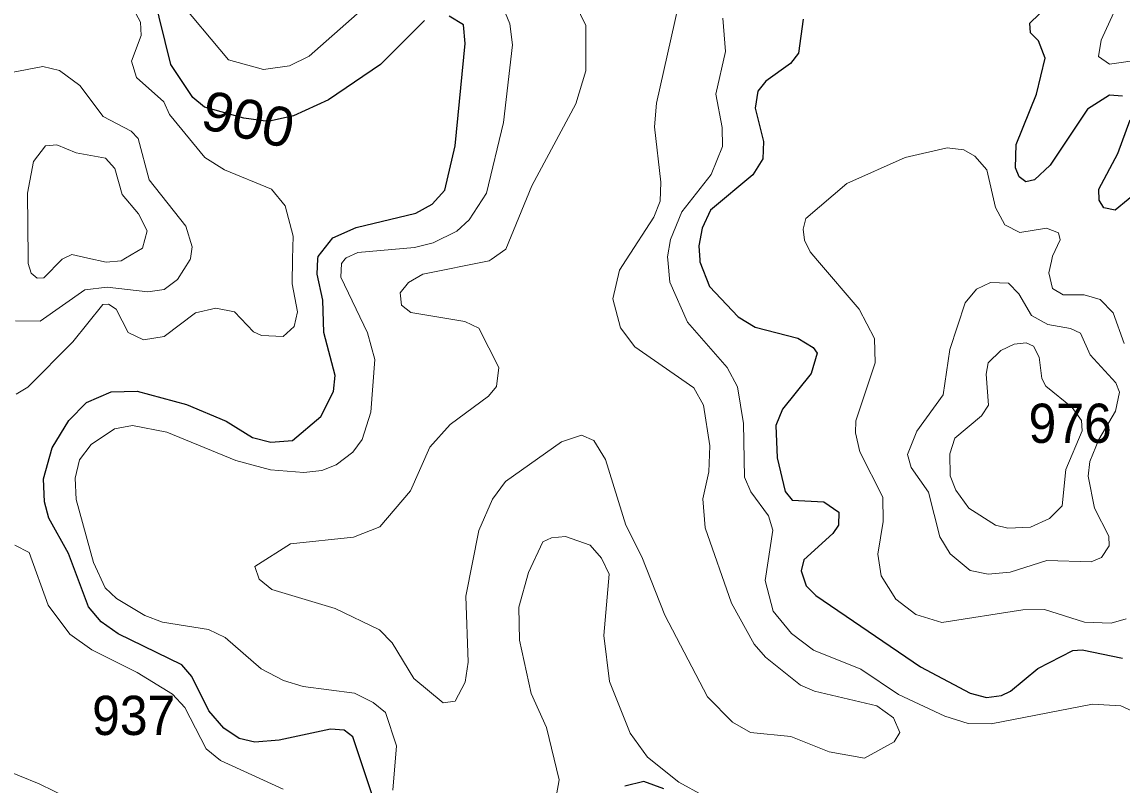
# Model space of a CAD drawing. Extents: x 473.9 to 500, y 7733.1 to 7760.8.
# Drawn here: x 488.002 to 490.243, y 7751.572 to 7753.127 of the extents above; entities that cross this region are included whole.
import ezdxf
from ezdxf.enums import TextEntityAlignment as Align

# ---------------------------------------------------------------- set-up
doc = ezdxf.new("R2010")
doc.units = 0
doc.header["$LTSCALE"] = 0.032
doc.layers.add('1', color=7, linetype='Continuous', lineweight=25)
doc.layers.add('2', color=7, linetype='Continuous', lineweight=13)
doc.layers.add('21', color=7, linetype='Continuous')
doc.layers.add('61', color=7, linetype='Continuous')

msp = doc.modelspace()

# ---------------------------------------------------------------- linework, layer by layer
at = {"layer": '1'}
for points in [[(490.0556, 7753.125), (490.1532, 7753.2201)], [(488.8218, 7753.1307), (488.7321, 7753.0411), (488.6264, 7752.9688), (488.555, 7752.9361), (488.5032, 7752.9247), (488.4537, 7752.9313), (488.3738, 7752.9536), (488.3498, 7752.9732), (488.3051, 7753.0408), (488.2698, 7753.1849)], [(488.3274, 7751.8169), (488.1979, 7751.88), (488.1633, 7751.9046), (488.1372, 7751.9352), (488.0963, 7752.0442), (488.0568, 7752.1157), (488.0478, 7752.149), (488.0456, 7752.196), (488.0636, 7752.259), (488.097, 7752.315), (488.1334, 7752.3518), (488.1833, 7752.3732), (488.2365, 7752.3751), (488.337, 7752.3475), (488.418, 7752.3137), (488.4715, 7752.2803), (488.5087, 7752.2708), (488.5527, 7752.2742), (488.6106, 7752.323), (488.6365, 7752.374), (488.6397, 7752.407), (488.6166, 7752.4946), (488.6147, 7752.5604), (488.6035, 7752.6132), (488.6049, 7752.6445), (488.6051, 7752.6495), (488.6355, 7752.6877), (488.6828, 7752.7085), (488.8045, 7752.738), (488.8375, 7752.7559), (488.8634, 7752.7845), (488.8847, 7752.8749), (488.905, 7753.0839), (488.9013, 7753.1217), (488.872, 7753.139)], [(489.5934, 7753.1335), (489.5841, 7753.0638), (489.5675, 7753.0428), (489.5174, 7753.0068), (489.501, 7752.9866), (489.4961, 7752.9521), (489.5129, 7752.8836), (489.5112, 7752.8484), (489.4908, 7752.8158), (489.4048, 7752.7439), (489.3879, 7752.7071), (489.3811, 7752.6711), (489.3831, 7752.6421), (489.3834, 7752.6382), (489.4026, 7752.5882), (489.4615, 7752.5264), (489.496, 7752.505), (489.5828, 7752.483), (489.6143, 7752.4641), (489.6219, 7752.4525), (489.6098, 7752.4108), (489.5518, 7752.3381), (489.5378, 7752.3047), (489.5407, 7752.2392), (489.5568, 7752.1702), (489.5715, 7752.1525), (489.6357, 7752.1492), (489.6665, 7752.1282), (489.6656, 7752.1019), (489.6544, 7752.0847), (489.5952, 7752.0308), (489.5893, 7752.0086), (489.5999, 7751.9782), (489.6195, 7751.9586), (489.8326, 7751.8129), (489.9337, 7751.7592), (489.9671, 7751.7506), (489.9979, 7751.7544), (490.0159, 7751.763), (490.0717, 7751.8095), (490.1434, 7751.8461), (490.1622, 7751.8474), (490.2441, 7751.8304)], [(490.2447, 7752.9761), (490.2176, 7752.9786), (490.1728, 7752.95), (490.0969, 7752.8355), (490.0648, 7752.8054), (490.0472, 7752.8018), (490.0337, 7752.8118), (490.0265, 7752.83), (490.0278, 7752.8775), (490.0693, 7752.9802), (490.0869, 7753.0535), (490.0735, 7753.0887), (490.0571, 7753.1051), (490.0556, 7753.125)], [(490.2823, 7752.7871), (490.2296, 7752.7436), (490.2061, 7752.7487), (490.1968, 7752.7641), (490.1963, 7752.7867), (490.2351, 7752.8591), (490.2597, 7752.9277)], [(488.7226, 7751.5297), (488.6762, 7751.6702), (488.6586, 7751.684), (488.6306, 7751.6855), (488.526, 7751.6632), (488.4764, 7751.659), (488.4444, 7751.667), (488.413, 7751.6879), (488.3824, 7751.7233), (488.3481, 7751.7934), (488.3274, 7751.8169)], [(489.3094, 7751.564), (489.2687, 7751.5793), (489.2303, 7751.5696)]]:
    msp.add_lwpolyline(points, dxfattribs=at)
at = {"layer": '2'}
for points in [[(488.7559, 7751.8615), (488.7305, 7751.888), (488.64, 7751.9317), (488.5112, 7751.9703), (488.4854, 7751.9919), (488.4765, 7752.0176), (488.5489, 7752.0636), (488.6775, 7752.0774), (488.7312, 7752.098), (488.7932, 7752.172), (488.8331, 7752.2604), (488.8744, 7752.3069), (488.9524, 7752.3649), (488.9684, 7752.3847), (488.9737, 7752.423), (488.9326, 7752.5035), (488.9042, 7752.5168), (488.7942, 7752.535), (488.7753, 7752.5504), (488.7723, 7752.5753), (488.7893, 7752.5964), (488.8185, 7752.6131), (488.9537, 7752.6407), (488.9576, 7752.6434), (488.988, 7752.664), (489.0404, 7752.7932), (489.1305, 7752.9609), (489.1511, 7753.0279), (489.1511, 7753.1201), (489.0847, 7753.2568)], [(490.3078, 7753.2568), (490.2264, 7753.1469), (490.2007, 7753.0907), (490.1957, 7753.0573), (490.2176, 7753.0414), (490.2886, 7753.0514)], [(487.9898, 7752.3685), (488.0137, 7752.383), (488.1051, 7752.4751), (488.1668, 7752.5516), (488.178, 7752.5522), (488.1939, 7752.5417), (488.2183, 7752.4944), (488.2492, 7752.4797), (488.2913, 7752.4864), (488.3552, 7752.5347), (488.3971, 7752.5442), (488.4348, 7752.5364), (488.4739, 7752.496), (488.4902, 7752.4885), (488.5337, 7752.4862), (488.5564, 7752.5067), (488.5632, 7752.5369), (488.5521, 7752.5938), (488.5533, 7752.6446), (488.5544, 7752.6909), (488.538, 7752.7526), (488.51, 7752.7868), (488.4143, 7752.826), (488.3747, 7752.8514), (488.3023, 7752.9391), (488.2911, 7752.965), (488.2352, 7753.0142), (488.2249, 7753.0477), (488.2447, 7753.1002), (488.2431, 7753.127), (488.2035, 7753.2021)], [(488.9767, 7753.17), (488.9959, 7753.1239), (489.0016, 7753.0806), (488.9832, 7752.9228), (488.9487, 7752.7787), (488.9128, 7752.7238), (488.8882, 7752.7009), (488.8398, 7752.677), (488.8018, 7752.6678), (488.6861, 7752.6573), (488.6623, 7752.6469), (488.6603, 7752.6443), (488.6532, 7752.635), (488.6512, 7752.6071), (488.7061, 7752.4938), (488.7209, 7752.4394), (488.7126, 7752.3322), (488.6951, 7752.2765), (488.6758, 7752.2508), (488.6422, 7752.2246), (488.6126, 7752.2128), (488.5761, 7752.2088), (488.5081, 7752.2147), (488.4373, 7752.2335), (488.297, 7752.2912), (488.2267, 7752.3046), (488.1903, 7752.298), (488.1425, 7752.2663), (488.119, 7752.2351), (488.1103, 7752.1978), (488.1119, 7752.1543), (488.1477, 7752.0256), (488.1716, 7751.974), (488.1947, 7751.9521), (488.252, 7751.9176), (488.2884, 7751.9042), (488.3816, 7751.8893), (488.4158, 7751.8727), (488.4891, 7751.8089), (488.5344, 7751.7852), (488.5747, 7751.7728), (488.6791, 7751.7594), (488.7176, 7751.7401), (488.7425, 7751.7196), (488.7652, 7751.6519), (488.7578, 7751.5612)], [(488.3133, 7753.1817), (488.4224, 7753.0501), (488.4941, 7753.0308), (488.5472, 7753.0379), (488.5873, 7753.0581), (488.685, 7753.1444)], [(489.3398, 7753.1619), (489.2948, 7752.9619), (489.291, 7752.9136), (489.3038, 7752.8012), (489.3022, 7752.762), (489.2892, 7752.7293), (489.2327, 7752.6425), (489.2191, 7752.6216), (489.2059, 7752.563), (489.2217, 7752.5037), (489.2507, 7752.4655), (489.3706, 7752.3815), (489.3904, 7752.3461), (489.4036, 7752.2634), (489.4011, 7752.2105), (489.3891, 7752.1554), (489.3937, 7752.0962), (489.4475, 7751.9425), (489.4937, 7751.8594), (489.5172, 7751.8328), (489.5882, 7751.7754), (489.617, 7751.763), (489.744, 7751.7335), (489.7777, 7751.7091), (489.7908, 7751.679), (489.7794, 7751.6598), (489.7187, 7751.6269), (489.6466, 7751.6398), (489.5685, 7751.6711), (489.4863, 7751.6787), (489.4494, 7751.6998), (489.399, 7751.7519), (489.3116, 7751.9185), (489.2651, 7752.0369), (489.232, 7752.1018), (489.1907, 7752.2357), (489.167, 7752.2741), (489.1422, 7752.2851), (489.1009, 7752.2719), (488.9874, 7752.1907), (488.9606, 7752.1545), (488.9327, 7752.091), (488.9065, 7751.957), (488.9107, 7751.8227), (488.9051, 7751.7817), (488.8848, 7751.7428), (488.86, 7751.7396), (488.8005, 7751.789), (488.7559, 7751.8615)], [(490.2993, 7751.7072), (490.2411, 7751.7335), (490.1832, 7751.737), (489.9767, 7751.6968), (489.9297, 7751.6974), (489.882, 7751.7122), (489.7881, 7751.7565), (489.7114, 7751.8084), (489.615, 7751.8471), (489.5702, 7751.8805), (489.5327, 7751.9264), (489.5161, 7751.9892), (489.5321, 7752.0915), (489.523, 7752.1209), (489.4867, 7752.1699), (489.4743, 7752.1993), (489.4718, 7752.3092), (489.4598, 7752.3836), (489.4388, 7752.4233), (489.3577, 7752.5153), (489.3219, 7752.5969), (489.3181, 7752.6423), (489.3175, 7752.6489), (489.3233, 7752.6838), (489.3462, 7752.7406), (489.4064, 7752.8163), (489.429, 7752.8735), (489.4285, 7752.9127), (489.4156, 7752.9802), (489.4356, 7753.0675), (489.4301, 7753.1351)], [(487.9805, 7753.0242), (488.0445, 7753.037), (488.078, 7753.0286), (488.1199, 7752.998), (488.1674, 7752.9345), (488.224, 7752.905), (488.2387, 7752.8902), (488.2611, 7752.8055), (488.3356, 7752.7113), (488.3486, 7752.6688), (488.345, 7752.6453), (488.3447, 7752.6431), (488.3189, 7752.6026), (488.2914, 7752.5821), (488.2583, 7752.5771), (488.1757, 7752.5867), (488.1302, 7752.5817), (488.0389, 7752.5175), (487.9883, 7752.5184)], [(490.2475, 7752.4719), (490.2252, 7752.5343), (490.1991, 7752.5616), (490.1665, 7752.5715), (490.1233, 7752.5709), (490.1018, 7752.5844), (490.0943, 7752.6163), (490.0994, 7752.6399), (490.1016, 7752.6501), (490.1173, 7752.6832), (490.1142, 7752.6975), (490.0895, 7752.7074), (490.0353, 7752.6986), (490.0049, 7752.7136), (489.9858, 7752.7493), (489.9682, 7752.8258), (489.9435, 7752.8541), (489.9209, 7752.8668), (489.8873, 7752.8706), (489.8016, 7752.8509), (489.6826, 7752.7982), (489.5993, 7752.7266), (489.5934, 7752.7053), (489.5962, 7752.6828), (489.6079, 7752.6591), (489.6231, 7752.6413), (489.7078, 7752.542), (489.7387, 7752.4822), (489.7403, 7752.4325), (489.7013, 7752.3145), (489.7, 7752.2896), (489.7091, 7752.2509), (489.7557, 7752.1585), (489.7564, 7752.1092), (489.7461, 7752.0428), (489.7527, 7751.9984), (489.7822, 7751.9507), (489.8233, 7751.9197), (489.876, 7751.9034), (490.0411, 7751.929), (490.0855, 7751.9298), (490.1668, 7751.9038), (490.2214, 7751.9021), (490.2516, 7751.9106)], [(489.0707, 7751.437), (489.0963, 7751.5823), (489.0706, 7751.6895), (489.0391, 7751.7586), (489.0153, 7751.8675), (489.0145, 7751.9344), (489.0341, 7752.0052), (489.0632, 7752.0676), (489.0805, 7752.076), (489.1095, 7752.0786), (489.1597, 7752.0608), (489.1826, 7752.0346), (489.1984, 7752.0017), (489.1873, 7751.8765), (489.1988, 7751.7828), (489.2412, 7751.6778), (489.2764, 7751.6286), (489.3401, 7751.5779), (489.3899, 7751.5506)], [(487.9871, 7752.0607), (488.0166, 7752.046), (488.0552, 7751.9384), (488.099, 7751.8794), (488.1442, 7751.8477), (488.2368, 7751.8012), (488.3084, 7751.757), (488.3333, 7751.7297), (488.3768, 7751.6458), (488.4064, 7751.6216), (488.5343, 7751.5632)], [(488.1594, 7751.5146), (488.0366, 7751.5745), (487.9558, 7751.6067)]]:
    msp.add_lwpolyline(points, dxfattribs=at)
for points in [[(488.2395, 7752.7364), (488.2058, 7752.7759), (488.1912, 7752.829), (488.1721, 7752.85), (488.112, 7752.8604), (488.0728, 7752.8769), (488.0498, 7752.8749), (488.0251, 7752.843), (488.0132, 7752.7787), (488.0142, 7752.6463), (488.0143, 7752.635), (488.0206, 7752.6156), (488.0327, 7752.6055), (488.046, 7752.6056), (488.0837, 7752.6441), (488.0878, 7752.646), (488.1032, 7752.6533), (488.1359, 7752.6459), (488.1731, 7752.6375), (488.2037, 7752.6404), (488.2125, 7752.6457), (488.2472, 7752.6664), (488.2567, 7752.7018)], [(490.1961, 7752.2766), (490.2298, 7752.3338), (490.2382, 7752.3729), (490.2309, 7752.3916), (490.1787, 7752.4487), (490.1591, 7752.4929), (490.1384, 7752.5029), (490.092, 7752.5106), (490.0589, 7752.529), (490.0334, 7752.5735), (490.0124, 7752.5952), (489.9751, 7752.5963), (489.9466, 7752.5825), (489.924, 7752.5552), (489.8927, 7752.4598), (489.8787, 7752.3673), (489.8251, 7752.2931), (489.8065, 7752.2458), (489.814, 7752.2193), (489.8489, 7752.1687), (489.8721, 7752.0776), (489.8933, 7752.0434), (489.9339, 7752.0092), (489.9708, 7752.0015), (490.0158, 7752.006), (490.0904, 7752.0294), (490.1804, 7752.0272), (490.2015, 7752.0357), (490.217, 7752.0593), (490.2166, 7752.0793), (490.1876, 7752.1366), (490.1746, 7752.2013), (490.1778, 7752.2314)], [(490.1215, 7752.141), (490.1288, 7752.2153), (490.1625, 7752.2941), (490.1607, 7752.3152), (490.1417, 7752.3416), (490.0879, 7752.3852), (490.0801, 7752.4009), (490.0743, 7752.4443), (490.0629, 7752.4666), (490.048, 7752.4733), (490.0239, 7752.4709), (489.9963, 7752.4579), (489.9709, 7752.4324), (489.9663, 7752.4097), (489.9716, 7752.3462), (489.9572, 7752.3244), (489.9029, 7752.279), (489.8924, 7752.2474), (489.8934, 7752.2025), (489.9048, 7752.173), (489.9314, 7752.1364), (489.9853, 7752.1018), (490.0105, 7752.0956), (490.0569, 7752.0974), (490.0953, 7752.1154)]]:
    msp.add_lwpolyline(points, close=True, dxfattribs=at)

# ---------------------------------------------------------------- texts
at = {"layer": '21', "width": 0.95}
for s, p in [('976', (490.0529, 7752.2694)), ('937', (488.1447, 7751.6739))]:
    msp.add_text(s, height=0.08, dxfattribs=at).set_placement(p)
at = {"layer": '61', "width": 1.05}
msp.add_text('900', height=0.08, rotation=346.921, dxfattribs=at).set_placement((488.4538, 7752.8902), align=Align.CENTER)

doc.saveas('drawing.dxf')
